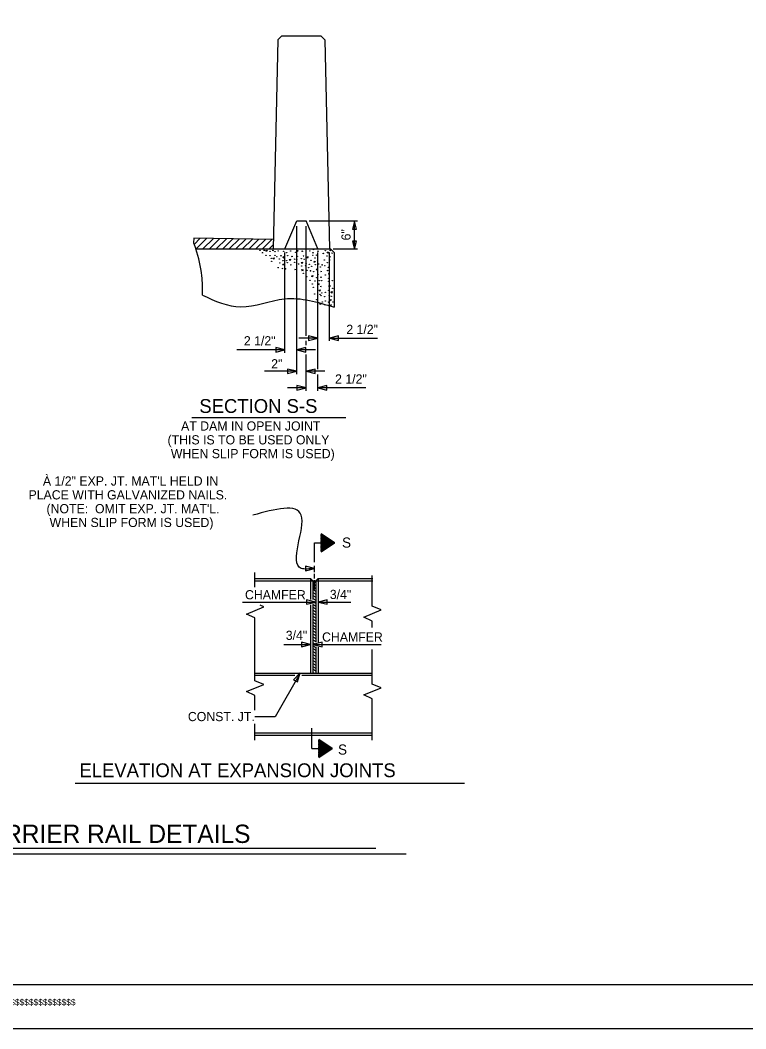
# Model space of a CAD drawing. Extents: x 0 to 217, y -54 to 96.
# Drawn here: x 125.75 to 135.65, y -53.79 to -40.02 of the extents above; entities that cross this region are included whole.
import ezdxf

# ---------------------------------------------------------------- set-up
doc = ezdxf.new("R2010")
doc.units = 0
for name, color, linetype in [('Arrowhead Terminators', 7, 'Continuous'), ('Box Beam', 7, 'Continuous'), ('Cored Slab Unit CELL', 7, 'Continuous'), ('Dimension Lines', 7, 'Continuous'), ('Mis Center Lines', 7, 'Continuous'), ('Mis Object Lines', 7, 'Continuous'), ('Miscellaneous Lines', 7, 'Continuous'), ('Plan Sheet CELL', 7, 'Continuous'), ('Plot Label CELL', 7, 'Continuous'), ('Plot Shape CELL', 7, 'Continuous'), ('Subtitle Text', 7, 'Continuous'), ('Sup Concrete Girder Lines', 7, 'Continuous'), ('Text', 7, 'Continuous'), ('Title Text', 7, 'Continuous'), ('User Information Notes', 7, 'Continuous')]:
    doc.layers.add(name, color=color, linetype=linetype)

msp = doc.modelspace()

# ---------------------------------------------------------------- linework, layer by layer
at = {"layer": 'Arrowhead Terminators'}
for points in [[(130.311, -42.762), (130.284, -42.871), (130.339, -42.871)], [(130.311, -43.144), (130.339, -43.035), (130.284, -43.035)], [(129.808, -44.36), (129.683, -44.329), (129.683, -44.391)], [(129.968, -44.36), (130.093, -44.391), (130.093, -44.329)], [(129.361, -44.521), (129.236, -44.489), (129.236, -44.552)], [(129.521, -44.521), (129.646, -44.552), (129.646, -44.489)], [(129.521, -44.814), (129.396, -44.783), (129.396, -44.846)], [(129.648, -44.814), (129.773, -44.846), (129.773, -44.783)], [(129.648, -45.039), (129.523, -45.008), (129.523, -45.071)], [(129.808, -45.039), (129.933, -45.071), (129.933, -45.008)], [(129.765, -47.504), (129.64, -47.473), (129.64, -47.536)], [(129.782, -47.964), (129.656, -47.933), (129.656, -47.995)], [(129.812, -47.964), (129.937, -47.995), (129.937, -47.933)], [(129.711, -48.544), (129.586, -48.513), (129.586, -48.576)], [(129.742, -48.544), (129.867, -48.576), (129.867, -48.513)], [(129.567, -48.93), (129.477, -49.024), (129.532, -49.055)]]:
    msp.add_lwpolyline(points, close=True, dxfattribs=at)
at = {"layer": 'Box Beam'}
for p, q in [((128.95, -48.933), (129.741, -48.933)), ((128.95, -48.963), (129.495, -48.963)), ((129.589, -48.963), (130.552, -48.963)), ((129.741, -48.933), (129.782, -48.933)), ((129.782, -48.933), (130.551, -48.933)), ((128.95, -49.75), (130.552, -49.75)), ((128.95, -49.78), (130.552, -49.78))]:
    msp.add_line(p, q, dxfattribs=at)
at = {"layer": 'Cored Slab Unit CELL'}
for p, q in [((129.265, -40.288), (129.201, -43.144)), ((129.313, -40.24), (129.265, -40.288)), ((129.856, -40.24), (129.313, -40.24)), ((129.856, -40.24), (129.904, -40.288)), ((129.904, -40.288), (129.968, -43.144))]:
    msp.add_line(p, q, dxfattribs=at)
at = {"layer": 'Dimension Lines'}
for p, q in [((129.689, -42.76), (130.351, -42.76)), ((130.311, -43.144), (130.311, -42.762)), ((129.521, -44.855), (129.521, -42.832)), ((129.648, -44.329), (129.648, -42.832)), ((129.361, -44.561), (129.361, -43.192)), ((129.808, -44.783), (129.808, -43.192)), ((129.968, -44.4), (129.968, -43.192)), ((130.02, -43.144), (130.351, -43.144)), ((129.808, -44.36), (129.552, -44.36)), ((129.648, -44.458), (129.648, -44.396)), ((129.968, -44.36), (130.626, -44.36)), ((129.361, -44.521), (128.703, -44.521)), ((129.776, -44.521), (129.521, -44.521)), ((129.648, -45.08), (129.648, -44.584)), ((129.521, -44.814), (129.081, -44.814)), ((129.904, -44.814), (129.648, -44.814)), ((129.808, -45.08), (129.808, -44.858)), ((129.648, -45.039), (129.396, -45.039)), ((130.466, -45.039), (129.808, -45.039)), ((129.762, -47.156), (130.038, -47.156)), ((129.762, -47.421), (129.762, -47.156)), ((128.782, -47.964), (129.782, -47.964)), ((129.812, -47.964), (130.262, -47.964)), ((129.344, -48.544), (129.711, -48.544)), ((129.742, -48.544), (130.674, -48.544)), ((129.727, -49.964), (129.727, -49.688)), ((129.727, -49.964), (130.003, -49.964))]:
    msp.add_line(p, q, dxfattribs=at)
for points in [[(129.856, -47.277), (130.038, -47.156), (129.856, -47.27), (129.856, -47.262), (130.038, -47.156), (129.856, -47.255), (129.856, -47.247), (130.038, -47.156), (129.856, -47.239), (129.856, -47.232), (130.038, -47.156), (129.856, -47.224), (129.856, -47.217), (130.038, -47.156), (129.856, -47.209), (129.856, -47.201), (130.038, -47.156), (129.856, -47.194), (129.856, -47.186), (130.038, -47.156), (129.856, -47.178), (129.856, -47.171), (130.038, -47.156), (129.856, -47.163), (129.856, -47.148), (130.038, -47.156), (129.856, -47.14), (129.856, -47.133), (130.038, -47.156), (129.856, -47.125), (129.856, -47.118), (130.038, -47.156), (129.856, -47.11), (129.856, -47.102), (130.038, -47.156), (129.856, -47.095), (129.856, -47.087), (130.038, -47.156), (129.856, -47.079), (129.856, -47.072), (130.038, -47.156), (129.856, -47.064), (129.856, -47.057), (130.038, -47.156), (129.856, -47.049), (129.856, -47.041), (130.038, -47.156), (129.856, -47.034), (129.856, -47.277), (130.038, -47.156), (129.856, -47.27)], [(129.567, -48.933), (129.228, -49.531), (128.951, -49.531)], [(129.821, -50.085), (130.003, -49.964), (129.821, -50.078), (129.821, -50.07), (130.003, -49.964), (129.821, -50.063), (129.821, -50.055), (130.003, -49.964), (129.821, -50.048), (129.821, -50.04), (130.003, -49.964), (129.821, -50.032), (129.821, -50.025), (130.003, -49.964), (129.821, -50.017), (129.821, -50.009), (130.003, -49.964), (129.821, -50.002), (129.821, -49.994), (130.003, -49.964), (129.821, -49.987), (129.821, -49.979), (130.003, -49.964), (129.821, -49.971), (129.821, -49.956), (130.003, -49.964), (129.821, -49.948), (129.821, -49.941), (130.003, -49.964), (129.821, -49.933), (129.821, -49.926), (130.003, -49.964), (129.821, -49.918), (129.821, -49.91), (130.003, -49.964), (129.821, -49.903), (129.821, -49.895), (130.003, -49.964), (129.821, -49.888), (129.821, -49.88), (130.003, -49.964), (129.821, -49.872), (129.821, -49.865), (130.003, -49.964), (129.821, -49.857), (129.821, -49.85), (130.003, -49.964), (129.821, -49.842), (129.821, -50.085), (130.003, -49.964), (129.821, -50.078)]]:
    msp.add_lwpolyline(points, dxfattribs=at)
msp.add_spline([(129.762, -47.504), (129.583, -47.504), (129.583, -46.778), (128.924, -46.778)], degree=3, dxfattribs=at)
at = {"layer": 'Mis Center Lines'}
for p, q in [((129.762, -47.556), (129.762, -47.468)), ((129.762, -47.641), (129.762, -47.579)), ((129.762, -47.791), (129.762, -47.665))]:
    msp.add_line(p, q, dxfattribs=at)
at = {"layer": 'Mis Object Lines'}
for p, q in [((129.361, -43.144), (129.521, -42.76)), ((129.521, -42.76), (129.648, -42.76)), ((129.808, -43.144), (129.648, -42.76)), ((128.95, -47.643), (129.71, -47.643)), ((129.741, -47.673), (129.71, -47.643)), ((129.711, -47.643), (129.711, -47.928)), ((129.782, -47.673), (129.813, -47.643)), ((129.812, -47.643), (129.812, -48.51)), ((129.813, -47.643), (130.56, -47.643)), ((128.95, -47.673), (129.741, -47.673)), ((129.741, -47.673), (129.741, -47.93)), ((129.741, -47.673), (129.741, -47.673)), ((129.741, -47.673), (129.781, -47.696)), ((129.741, -47.673), (129.782, -47.673)), ((129.741, -47.713), (129.781, -47.736)), ((129.741, -47.754), (129.781, -47.777)), ((129.782, -47.673), (130.56, -47.673)), ((129.782, -47.673), (129.782, -48.513)), ((129.741, -47.794), (129.781, -47.817)), ((129.741, -47.834), (129.781, -47.857)), ((129.741, -47.875), (129.781, -47.898)), ((129.741, -47.915), (129.781, -47.938)), ((129.711, -48), (129.711, -48.934)), ((129.741, -47.955), (129.781, -47.978)), ((129.741, -47.995), (129.781, -48.019)), ((129.741, -47.999), (129.741, -48.933)), ((129.741, -48.036), (129.781, -48.059)), ((129.741, -48.076), (129.781, -48.099)), ((129.741, -48.116), (129.781, -48.139)), ((129.741, -48.157), (129.781, -48.18)), ((129.741, -48.197), (129.781, -48.22)), ((129.741, -48.237), (129.781, -48.26)), ((129.741, -48.278), (129.781, -48.301)), ((129.741, -48.318), (129.781, -48.341)), ((129.741, -48.358), (129.781, -48.381)), ((129.741, -48.399), (129.781, -48.422)), ((129.741, -48.439), (129.781, -48.462)), ((129.741, -48.479), (129.781, -48.502)), ((129.741, -48.519), (129.781, -48.542)), ((129.741, -48.56), (129.781, -48.583)), ((129.741, -48.6), (129.781, -48.623)), ((129.782, -48.575), (129.782, -48.933)), ((129.812, -48.578), (129.812, -48.933)), ((129.741, -48.64), (129.781, -48.663)), ((129.741, -48.681), (129.781, -48.704)), ((129.741, -48.721), (129.781, -48.744)), ((129.741, -48.761), (129.781, -48.784)), ((129.741, -48.802), (129.781, -48.825)), ((129.741, -48.842), (129.781, -48.865)), ((129.741, -48.882), (129.781, -48.905)), ((129.741, -48.922), (129.76, -48.933))]:
    msp.add_line(p, q, dxfattribs=at)
for points in [[(128.95, -47.763), (128.95, -47.559)], [(130.552, -48.306), (130.552, -48.223), (130.436, -48.17), (130.673, -48.071), (130.552, -48.021), (130.552, -47.601)], [(128.95, -48.264), (128.95, -48.181), (128.835, -48.128), (129.071, -48.029), (129.021, -48.008)], [(128.95, -49.441), (128.95, -49.24), (128.835, -49.187), (129.071, -49.088), (128.95, -49.038), (128.95, -48.26)], [(130.552, -48.313), (130.552, -48.306)], [(130.552, -49.852), (130.552, -49.286), (130.436, -49.233), (130.673, -49.134), (130.552, -49.084), (130.552, -48.612)], [(128.95, -49.852), (128.95, -49.627)]]:
    msp.add_lwpolyline(points, dxfattribs=at)
at = {"layer": 'Miscellaneous Lines'}
for p, q in [((129.201, -43.016), (128.115, -42.994)), ((128.122, -43.081), (128.205, -42.998)), ((128.15, -43.144), (128.296, -42.998)), ((128.24, -43.144), (128.384, -43)), ((128.33, -43.144), (128.473, -43.001)), ((128.421, -43.144), (128.561, -43.003)), ((128.511, -43.144), (128.65, -43.005)), ((128.601, -43.144), (128.738, -43.007)), ((128.692, -43.144), (128.827, -43.009)), ((128.782, -43.144), (128.916, -43.01)), ((128.873, -43.144), (129.004, -43.012)), ((128.963, -43.144), (129.093, -43.014)), ((129.053, -43.144), (129.181, -43.016)), ((129.144, -43.144), (129.201, -43.086))]:
    msp.add_line(p, q, dxfattribs=at)
msp.add_lwpolyline([(128.115, -42.994), (128.114, -43.06), (128.146, -43.144)], dxfattribs=at)
at = {"layer": 'Plan Sheet CELL'}
msp.add_line((118.765, -53.185), (150.766, -53.185), dxfattribs=at)
at = {"layer": 'Plot Shape CELL'}
msp.add_lwpolyline([(117.711, -31.791), (150.775, -31.791), (150.775, -53.791), (117.711, -53.791)], close=True, dxfattribs=at)
at = {"layer": 'Subtitle Text'}
for p, q in [((128.088, -45.445), (130.19, -45.445)), ((126.499, -50.436), (131.81, -50.436))]:
    msp.add_line(p, q, dxfattribs=at)
at = {"layer": 'Sup Concrete Girder Lines'}
for points in [[(128.146, -43.144), (128.882, -43.144), (129.984, -43.144), (130.032, -43.192), (130.032, -43.938)], [(129.108, -43.179), (129.096, -43.166), (129.116, -43.161), (129.108, -43.179)], [(129.529, -43.179), (129.521, -43.161), (129.536, -43.164), (129.529, -43.179)], [(129.946, -43.204), (129.939, -43.187), (129.954, -43.189), (129.946, -43.204)], [(129.209, -43.282), (129.194, -43.27), (129.214, -43.265), (129.209, -43.282)], [(129.345, -43.267), (129.33, -43.255), (129.35, -43.247), (129.345, -43.267)], [(129.34, -43.368), (129.33, -43.35), (129.348, -43.35), (129.34, -43.368)], [(129.433, -43.3), (129.42, -43.287), (129.438, -43.282), (129.433, -43.3)], [(129.597, -43.343), (129.581, -43.33), (129.602, -43.325), (129.597, -43.343)], [(129.67, -43.27), (129.662, -43.249), (129.677, -43.252), (129.67, -43.27)], [(129.765, -43.33), (129.753, -43.317), (129.773, -43.312), (129.765, -43.33)], [(129.602, -43.446), (129.592, -43.426), (129.609, -43.428), (129.602, -43.446)], [(129.737, -43.526), (129.722, -43.514), (129.742, -43.506), (129.737, -43.526)], [(129.798, -43.431), (129.785, -43.418), (129.803, -43.413), (129.798, -43.431)], [(129.82, -43.637), (129.81, -43.617), (129.828, -43.619), (129.82, -43.637)], [(129.966, -43.66), (129.966, -43.642), (129.984, -43.649), (129.966, -43.66)], [(129.836, -43.72), (129.823, -43.707), (129.841, -43.702), (129.836, -43.72)], [(129.999, -43.745), (129.986, -43.732), (130.007, -43.725), (129.999, -43.745)], [(129.843, -43.901), (129.836, -43.883), (129.853, -43.883), (129.843, -43.901)], [(129.984, -43.853), (129.974, -43.841), (129.991, -43.833), (129.984, -43.853)]]:
    msp.add_lwpolyline(points, dxfattribs=at)
for centre in [(129.02, -43.162), (129.054, -43.196), (129.077, -43.164), (129.103, -43.231), (129.155, -43.176), (129.156, -43.234), (129.197, -43.164), (129.223, -43.182), (129.223, -43.231), (129.268, -43.173), (129.305, -43.237), (129.343, -43.176), (129.383, -43.194), (129.398, -43.236), (129.44, -43.173), (129.508, -43.19), (129.596, -43.174), (129.614, -43.241), (129.7, -43.172), (129.741, -43.232), (129.742, -43.196), (129.749, -43.151), (129.793, -43.228), (129.81, -43.174), (129.883, -43.205), (129.912, -43.166), (129.936, -43.24), (129.978, -43.164), (130.004, -43.201), (129.176, -43.271), (129.18, -43.311), (129.25, -43.247), (129.285, -43.28), (129.291, -43.336), (129.332, -43.303), (129.383, -43.302), (129.393, -43.33), (129.439, -43.36), (129.458, -43.246), (129.49, -43.283), (129.493, -43.325), (129.52, -43.291), (129.528, -43.244), (129.546, -43.35), (129.584, -43.277), (129.589, -43.375), (129.623, -43.285), (129.641, -43.372), (129.646, -43.339), (129.693, -43.352), (129.715, -43.299), (129.724, -43.379), (129.77, -43.267), (129.776, -43.357), (129.805, -43.309), (129.82, -43.35), (129.869, -43.36), (129.899, -43.293), (129.905, -43.372), (129.94, -43.329), (129.969, -43.295), (129.977, -43.251), (129.268, -43.397), (129.328, -43.41), (129.368, -43.415), (129.499, -43.424), (129.613, -43.476), (129.663, -43.435), (129.685, -43.4), (129.709, -43.442), (129.753, -43.454), (129.81, -43.491), (129.844, -43.39), (129.853, -43.451), (129.913, -43.499), (129.943, -43.438), (129.951, -43.395), (129.96, -43.483), (129.659, -43.522), (129.704, -43.571), (129.735, -43.622), (129.769, -43.58), (129.795, -43.536), (129.83, -43.576), (129.852, -43.656), (129.853, -43.529), (129.862, -43.575), (129.957, -43.543), (129.958, -43.585), (130.006, -43.578), (129.747, -43.667), (129.765, -43.757), (129.838, -43.763), (129.852, -43.781), (129.864, -43.746), (129.902, -43.794), (129.913, -43.737), (129.956, -43.708), (129.965, -43.777), (129.994, -43.791), (130.011, -43.681), (129.794, -43.835), (129.871, -43.868), (129.907, -43.906), (129.911, -43.853), (129.954, -43.87), (129.959, -43.916), (129.991, -43.909), (130.018, -43.868)]:
    msp.add_circle(centre, 0.00279, dxfattribs=at)
for points in [[(128.234, -43.774), (128.227, -43.509), (128.146, -43.144)], [(128.234, -43.774), (128.756, -43.934), (129.355, -43.824), (130.032, -43.938)]]:
    msp.add_spline(points, degree=3, dxfattribs=at)
at = {"layer": 'Title Text'}
for p, q in [((130.602, -51.331), (121.096, -51.331)), ((131.017, -51.408), (120.681, -51.408))]:
    msp.add_line(p, q, dxfattribs=at)
at = {"layer": 'User Information Notes'}
msp.add_line((130.032, -43.144), (130.032, -43.144), dxfattribs=at)

# ---------------------------------------------------------------- texts
at = {"layer": 'Plot Label CELL'}
msp.add_text('$$$$$$$$$$$$$$$$$$$$$$$DGN$$$$$$$$$$$$$$$$$$$$$$$', height=0.08556, dxfattribs=at).set_placement((123.321, -53.47))
at = {"layer": 'Subtitle Text'}
for s, height, p in [('SECTION S-S', 0.1886, (128.192, -45.382)), ('ELEVATION AT EXPANSION JOINTS', 0.18863, (126.555, -50.355))]:
    msp.add_text(s, height=height, dxfattribs=at).set_placement(p)
at = {"layer": 'Text'}
msp.add_text('6"', height=0.1254, rotation=90, dxfattribs=at).set_placement((130.257, -43.027))
for s, height, p in [('2 1/2"', 0.1254, (130.198, -44.304)), ('2 1/2"', 0.1254, (128.8, -44.46)), ('2"', 0.1254, (129.173, -44.774)), ('2 1/2"', 0.1254, (130.045, -44.981)), ('AT DAM IN OPEN JOINT', 0.12544, (127.943, -45.623)), ('(THIS IS TO BE USED ONLY', 0.12544, (127.758, -45.812)), ('WHEN SLIP FORM IS USED)', 0.12544, (127.803, -46)), ('À 1/2" EXP. JT. MAT\'L HELD IN', 0.12544, (126.057, -46.374)), ('PLACE WITH GALVANIZED NAILS.', 0.12544, (125.861, -46.563)), ("(NOTE:  OMIT EXP. JT. MAT'L.", 0.12544, (126.106, -46.752)), ('WHEN SLIP FORM IS USED)', 0.12544, (126.148, -46.94)), ('S', 0.138, (130.14, -47.221)), ('CHAMFER', 0.1254, (128.815, -47.927)), ('3/4"', 0.1254, (129.973, -47.923)), ('3/4"', 0.1254, (129.372, -48.481)), ('CHAMFER', 0.1254, (129.867, -48.504)), ('CONST. JT.', 0.1254, (128.036, -49.59)), ('S', 0.138, (130.085, -50.047))]:
    msp.add_text(s, height=height, dxfattribs=at).set_placement(p)
at = {"layer": 'Title Text'}
msp.add_text('VERTICAL CONCRETE BARRIER RAIL DETAILS', height=0.25, dxfattribs=at).set_placement((121.385, -51.253))

doc.saveas('drawing.dxf')
